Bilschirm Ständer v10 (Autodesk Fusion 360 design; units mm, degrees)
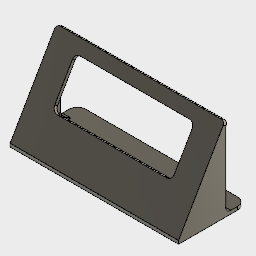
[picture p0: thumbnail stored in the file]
sketch "Skizze1"
  line L1 (-50, -20) -> (50, -20)
  line L2 (-50, 20) -> (-50, -20)
  line L3 (50, 20) -> (-50, 20)
  line L4 (50, -20) -> (50, 20)
  line L5 (-50, 20) -> (50, -20)
  line L6 (50, 20) -> (-50, -20)
  point P4 (-50, 20)
  point P5 (50, 20)
  point P3 (-50, -20)
  dimension "d1" distance P4 P5 = 100
  dimension "d2" distance P3 P4 = 40
extrude "Extrusion1" new body sketch "Skizze1" profile of L1 L2 L3 L4 blind 2
work_plane "Arbeitsebene" RotateAngle 60
sketch "Skizze2" plane through (0, -20, 2) normal (0, -0.866, 0.5) x axis (1, 0, 0)
  line L1 (-50, 0) -> (50, 0)
  line L2 (-50, 55) -> (-50, 0)
  line L3 (50, 55) -> (-50, 55)
  line L4 (50, 0) -> (50, 55)
  line L5 (-50, 55) -> (50, 0)
  line L6 (50, 55) -> (-50, 0)
  point P3 (-50, 0)
  point P4 (-50, 55)
  dimension "d6" distance P3 P4 = 55
extrude "Extrusion2" add sketch "Skizze2" profile of L1 L2 L3 L4 along a picked direction blind -2
sketch "Skizze3" plane through (0, -15.866, 9.1603) normal (0, -0.866, 0.5) x axis (1, 0, 0)
  line L1 (-50, 46.7321) -> (50, 46.7321)
  line L2 (-50, -8.2679) -> (-50, 46.7321)
  line L3 (50, -8.2679) -> (-50, -8.2679)
  line L4 (50, 46.7321) -> (50, -8.2679)
  line L5 (-37.5, 10.7321) -> (37.5, 10.7321)
  line L6 (-37.5, 41.7321) -> (-37.5, 10.7321)
  line L7 (37.5, 41.7321) -> (-37.5, 41.7321)
  line L8 (37.5, 10.7321) -> (37.5, 41.7321)
  line L9 (-37.5, 41.7321) -> (37.5, 10.7321)
  line L10 (37.5, 41.7321) -> (-37.5, 10.7321)
  line L11 (0, -8.2679) -> (0, 46.7321)
  line L12 (35.5, 39.7321) -> (-35.5, 39.7321)
  line L13 (35.5, 12.7321) -> (35.5, 39.7321)
  line L14 (-35.5, 12.7321) -> (35.5, 12.7321)
  line L15 (-35.5, 39.7321) -> (-35.5, 12.7321)
  circle C1 centre (-37.5, 41.7321) radius 2.5
  circle C2 centre (37.5, 41.7321) radius 2.5
  circle C3 centre (37.5, 10.7321) radius 2.5
  circle C4 centre (-37.5, 10.7321) radius 2.5
  circle C5 centre (-37.5, 41.7321) radius 1.4
  circle C6 centre (37.5, 41.7321) radius 1.4
  circle C7 centre (37.5, 10.7321) radius 1.4
  circle C8 centre (-37.5, 10.7321) radius 1.4
  point P8 (-37.5, 41.7321)
  point P9 (37.5, 41.7321)
  point P6 (37.5, 10.7321)
  dimension "d9" distance P8 P9 = 75
  dimension "d10" distance P6 P9 = 31
  dimension "d11" diameter C4 = 5
  dimension "d12" diameter C5 = 2.8
  dimension "d17" = 2
  dimension "d44" distance L1 L12 = 7
extrude "Extrusion5" cut sketch "Skizze3" profile of L12 L15 L13 L14 along a picked direction to an object
extrude "Extrusion3" add sketch "Skizze3" profile of C1 C2 C3 C4 C5 C6 C7 C8 along a picked direction blind 5
extrude "Extrusion4" add sketch "Skizze3" profile of C5 C6 C7 C8 along a picked direction blind 8
fillet "Abrundung1" radius 1
sketch "Skizze6" plane through (50, 0, 0) normal (1, 0, 0) x axis (0, 1, 0)
  line L1 (-20, 0) -> (-20, 2)
  line L2 (20, 0) -> (-20, 0)
  line L3 (20, 2) -> (20, 0)
  line L4 (-17.6906, 2) -> (20, 2)
  line L5 (9.2321, 48.6314) -> (-17.6906, 2)
  line L6 (7.5, 49.6314) -> (9.2321, 48.6314)
  line L7 (-20, 2) -> (7.5, 49.6314)
  line L8 (8, 2) -> (8, 46.4974)
  point P3 (-20, 0)
  dimension "d32" distance P3 L8 = 28
extrude "Extrusion6" add sketch "Skizze6" profile of L4 L5 L8 against normal blind 2
sketch "Skizze7" plane through (-50, 0, 0) normal (-1, 0, 0) x axis (0, -1, 0)
  line L1 (-20, 2) -> (17.6906, 2)
  line L2 (-20, 0) -> (-20, 2)
  line L3 (20, 0) -> (-20, 0)
  line L4 (20, 2) -> (20, 0)
  line L5 (-7.5, 49.6314) -> (20, 2)
  line L6 (-9.2321, 48.6314) -> (-7.5, 49.6314)
  line L7 (17.6906, 2) -> (-9.2321, 48.6314)
  line L8 (-8, 2) -> (-8, 46.4974)
  point P5 (20, 0)
  point P11 (-8, 2)
  dimension "d31" distance P5 P11 = 28
extrude "Extrusion7" add sketch "Skizze7" profile of L1 L7 L8 against normal blind 2
fillet "Abrundung3" radius 2
fillet "Abrundung4" radius 3
sketch "Skizze8" plane through (-50, 0, 0) normal (-1, 0, 0) x axis (0, -1, 0)
  line L1 (-15.3553, 34.5269) -> (-13.9411, 35.9411)
  line L2 (-8, 5) -> (-8, 27.1716)
  line L3 (-20, 2) -> (-11, 2)
  line L4 (-20, 0) -> (-20, 2)
  line L5 (20, 0) -> (-20, 0)
  line L6 (20, 2) -> (20, 0)
  line L7 (-13.9411, 35.9411) -> (20, 2)
  line L8 (-14.6482, 28.163) -> (-10.4056, 32.4056)
  line L9 (-7.5772, 21.0919) -> (-14.6482, 28.163)
  line L10 (-3.3345, 25.3345) -> (-7.5772, 21.0919)
  line L11 (-11.1127, 40.1838) -> (-8.2843, 37.3553)
  line L12 (-8, 27.1716) -> (-15.3553, 34.5269)
  arc A1 centre (-11, 5) radius 3 clockwise from (-8, 5) to (-11, 2)
  point P16 (-9.6985, 38.7696)
  point P13 (-14.6482, 28.163)
  point P14 (-7.5772, 21.0919)
  dimension "d28" distance L8 P16 = 4
  dimension "d29" distance P13 P14 = 10
  dimension "d30" distance L9 L11 = 11
fillet "Abrundung6" radius 1
extrude "Extrusion8" cut sketch "Skizze8" profile of L7 L8 L9 L10 to an object
fillet "Abrundung7" radius 2
fillet "Abrundung9" radius 5
sketch "Skizze9" plane through (0, -14.134, 8.1603) normal (0, 0.866, -0.5) x axis (-1, 0, 0)
  line L1 (-32.5, 12.7321) -> (32.5, 12.7321)
  line L2 (32.5, 39.7321) -> (-32.5, 39.7321)
  line L3 (45, 45.0718) -> (45, -5.3812)
  line L4 (-48, 46.7321) -> (48, 46.7321)
  line L5 (-45, -5.3812) -> (-45, 45.0718)
  line L6 (45, -5.3812) -> (-45, -5.3812)
  line L7 (35.5, 15.7321) -> (35.5, 36.7321)
  line L8 (-35.5, 36.7321) -> (-35.5, 15.7321)
  line L9 (49.9709, 45.0718) -> (45, 45.0718)
  line L10 (-45, 45.0718) -> (-49.9709, 45.0718)
  arc A1 centre (48, 44.7321) radius 2 clockwise from (48, 46.7321) to (49.9709, 45.0718)
  arc A2 centre (-48, 44.7321) radius 2 clockwise from (-49.9709, 45.0718) to (-48, 46.7321)
  circle C1 centre (37.5, 41.7321) radius 2.5
  circle C2 centre (37.5, 10.7321) radius 2.5
  circle C3 centre (-37.5, 10.7321) radius 2.5
  circle C4 centre (-37.5, 41.7321) radius 2.5
  arc A3 centre (32.5, 15.7321) radius 3 clockwise from (35.5, 15.7321) to (32.5, 12.7321)
  arc A4 centre (-32.5, 15.7321) radius 3 clockwise from (-32.5, 12.7321) to (-35.5, 15.7321)
  arc A5 centre (-32.5, 36.7321) radius 3 clockwise from (-35.5, 36.7321) to (-32.5, 39.7321)
  arc A6 centre (32.5, 36.7321) radius 3 clockwise from (32.5, 39.7321) to (35.5, 36.7321)
extrude "Extrusion9" add sketch "Skizze9" profile of C1 C4 along normal blind 5
sketch "Skizze10" plane through (0, -9.8038, 5.6603) normal (0, 0.866, -0.5) x axis (-1, 0, 0)
  line L1 (37.5, 41.7321) -> (37.5, 10.7321)
  circle C1 centre (-37.5, 41.7321) radius 2.5
  circle C2 centre (-37.5, 41.7321) radius 1.4
  circle C3 centre (-37.5, 10.7321) radius 1.4
  circle C4 centre (37.5, 41.7321) radius 1.4
  circle C5 centre (37.5, 10.7321) radius 1.4
  circle C6 centre (-37.5, 41.7321) radius 2.5
  circle C7 centre (37.5, 41.7321) radius 2.5
  circle C8 centre (-37.5, 41.7321) radius 2.5
  circle C9 centre (37.5, 41.7321) radius 2.5
  dimension "d46" diameter C2 = 2.8
extrude "Extrusion10" cut sketch "Skizze10" profile of C2 C3 C4 C5 along a picked direction to an object
fillet "Abrundung10" radius 1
